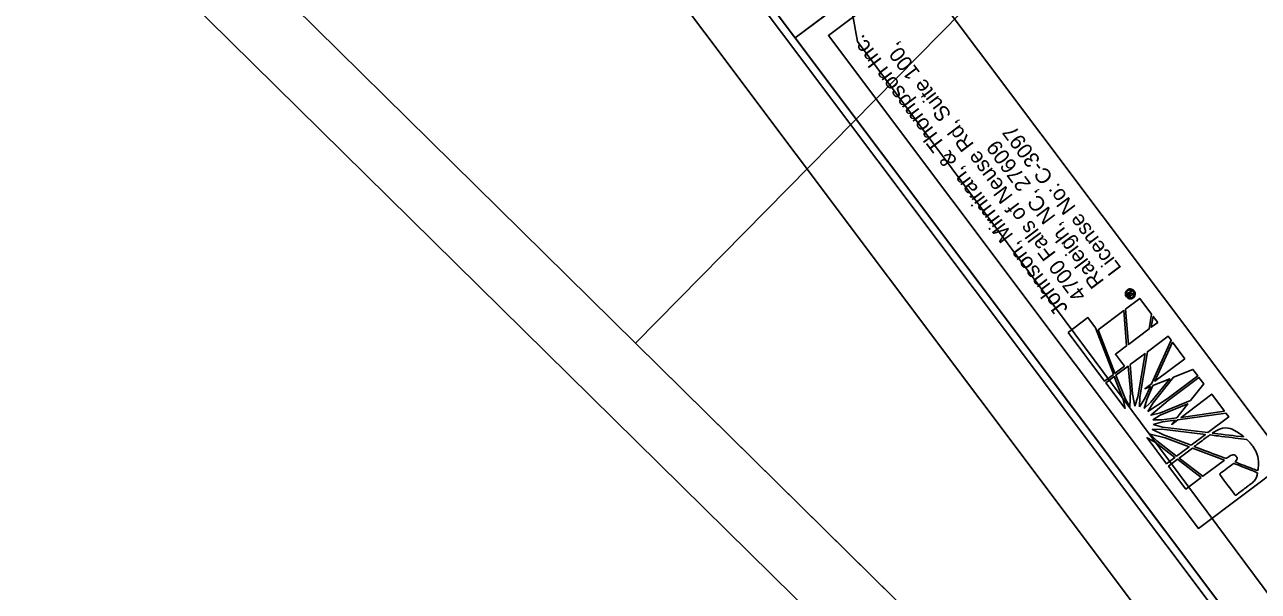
# Model space of a CAD drawing. Extents: x 1265100 to 1267089, y 771887 to 773927.
# Drawn here: x 1265100.1 to 1265500.7, y 772893.1 to 773077 of the extents above; entities that cross this region are included whole.
import ezdxf

# ---------------------------------------------------------------- set-up
doc = ezdxf.new("R2010")
doc.units = 0
for name, color, linetype in [('Exist Utilities Power Pole Cogo Elevation', 7, 'Continuous'), ('Prop Conc 1ft 6in Curb and Gutter', 7, 'Continuous'), ('Prop Conc 4in Sidewalk', 7, 'Continuous'), ('Prop EOT', 7, 'Continuous'), ('Prop Horizontal Alignment Station Label', 7, 'Continuous'), ('Prop Plan Preparation Crest', 7, 'Continuous'), ('Prop Plan Preparation Watershed Post Construction', 7, 'Continuous'), ('Typical Terminator CELL', 7, 'Continuous')]:
    doc.layers.add(name, color=color, linetype=linetype)

msp = doc.modelspace()

# ---------------------------------------------------------------- linework, layer by layer
at = {"layer": 'Exist Utilities Power Pole Cogo Elevation'}
for p, q in [((1265460.15, 772990.34), (1265460.14, 772990.35)), ((1265460.15, 772990.34), (1265460.4, 772990.53)), ((1265460.4, 772990.53), (1265460.15, 772990.34)), ((1265460.39, 772990.54), (1265460.4, 772990.53)), ((1265462.25, 772988.1), (1265457.61, 772984.6)), ((1265457.89, 772988.63), (1265458.13, 772988.81)), ((1265458.13, 772988.81), (1265457.89, 772988.63)), ((1265458.56, 772989.14), (1265458.51, 772989.22)), ((1265458.56, 772989.14), (1265458.78, 772989.31)), ((1265458.78, 772989.31), (1265458.56, 772989.14)), ((1265458.91, 772988.67), (1265458.56, 772989.14)), ((1265458.76, 772989.34), (1265458.78, 772989.31)), ((1265458.78, 772989.31), (1265458.94, 772989.1)), ((1265460.06, 772989.54), (1265458.91, 772988.67)), ((1265458.94, 772989.1), (1265459.21, 772989.3)), ((1265459.05, 772989.51), (1265459.04, 772989.52)), ((1265459.05, 772989.51), (1265459.26, 772989.67)), ((1265459.26, 772989.67), (1265459.05, 772989.51)), ((1265459.21, 772989.3), (1265459.05, 772989.51)), ((1265459.25, 772989.68), (1265459.26, 772989.67)), ((1265459.26, 772989.67), (1265459.42, 772989.46)), ((1265459.42, 772989.46), (1265459.86, 772989.8)), ((1265459.86, 772989.8), (1265460.06, 772989.54)), ((1265466.06, 772983.02), (1265462.25, 772988.1)), ((1265457.02, 772984.17), (1265448.77, 772977.95)), ((1265457.95, 772972.72), (1265457.02, 772984.17)), ((1265457.61, 772984.6), (1265458.56, 772973.18)), ((1265465.25, 772978.22), (1265466.06, 772983.02)), ((1265466.62, 772982.28), (1265465.98, 772978.77)), ((1265468.08, 772980.35), (1265466.62, 772982.28)), ((1265445.37, 772981.88), (1265438.93, 772977.03)), ((1265447.89, 772978.53), (1265445.37, 772981.88)), ((1265453.74, 772963.54), (1265447.89, 772978.53)), ((1265458.56, 772973.18), (1265465.25, 772978.22)), ((1265465.98, 772978.77), (1265468.08, 772980.35)), ((1265438.93, 772977.03), (1265450.76, 772961.3)), ((1265448.77, 772977.95), (1265454.18, 772963.87)), ((1265471.44, 772975.88), (1265464.73, 772970.82)), ((1265466.09, 772960.43), (1265472.44, 772974.56)), ((1265472.44, 772974.56), (1265471.44, 772975.88)), ((1265454.35, 772970.02), (1265457.95, 772972.72)), ((1265463.95, 772970.24), (1265459.16, 772966.64)), ((1265461.62, 772956.15), (1265463.95, 772970.24)), ((1265464.73, 772970.82), (1265462.24, 772956.1)), ((1265472.86, 772973.91), (1265467.17, 772961.24)), ((1265476.89, 772968.55), (1265472.86, 772973.91)), ((1265454.23, 772963.91), (1265457.24, 772966.18)), ((1265457.24, 772966.18), (1265454.35, 772970.02)), ((1265458.49, 772966.13), (1265454.49, 772963.2)), ((1265459.2, 772958), (1265458.49, 772966.13)), ((1265459.16, 772966.64), (1265459.91, 772957.13)), ((1265467.17, 772961.24), (1265476.89, 772968.55)), ((1265450.76, 772961.3), (1265453.65, 772963.48)), ((1265453.93, 772962.77), (1265451.24, 772960.75)), ((1265453.65, 772963.48), (1265453.74, 772963.54)), ((1265456.85, 772955.27), (1265453.93, 772962.77)), ((1265454.18, 772963.87), (1265454.23, 772963.91)), ((1265454.49, 772963.2), (1265457.55, 772955.47)), ((1265473.15, 772962.56), (1265466.55, 772954.24)), ((1265471.09, 772955.51), (1265481.06, 772963.01)), ((1265481.46, 772962.48), (1265471.49, 772954.98)), ((1265479.5, 772965.09), (1265473.15, 772962.56)), ((1265481.06, 772963.01), (1265479.5, 772965.09)), ((1265483.01, 772960.43), (1265481.46, 772962.48)), ((1265451.24, 772960.75), (1265457.44, 772952.43)), ((1265463.91, 772958.78), (1265466.09, 772960.43)), ((1265463.91, 772955.67), (1265465.68, 772959.52)), ((1265465.68, 772959.52), (1265463.91, 772958.78)), ((1265466.53, 772959.85), (1265464.48, 772955.27)), ((1265465.88, 772954.45), (1265471.97, 772962.07)), ((1265471.97, 772962.07), (1265466.53, 772959.85)), ((1265478.67, 772954.97), (1265483.01, 772960.43)), ((1265457.44, 772952.43), (1265456.85, 772955.27)), ((1265457.55, 772955.47), (1265458.99, 772952.94)), ((1265458.99, 772952.94), (1265459.2, 772958)), ((1265459.91, 772957.13), (1265460.64, 772953.16)), ((1265460.64, 772953.16), (1265461.62, 772956.15)), ((1265462.24, 772956.1), (1265462.2, 772952.96)), ((1265462.2, 772952.96), (1265463.91, 772955.67)), ((1265464.48, 772955.27), (1265463.67, 772952.4)), ((1265463.67, 772952.4), (1265465.88, 772954.45)), ((1265464.9, 772951.45), (1265471.09, 772955.51)), ((1265466.55, 772954.24), (1265464.9, 772951.45)), ((1265471.49, 772954.98), (1265465.83, 772950.22)), ((1265469, 772950.99), (1265478.67, 772954.97)), ((1265485.59, 772957.08), (1265475.65, 772949.52)), ((1265489.79, 772951.5), (1265485.59, 772957.08)), ((1265465.83, 772950.22), (1265469, 772950.99)), ((1265468.89, 772950.26), (1265466.43, 772948.73)), ((1265477.82, 772953.94), (1265468.89, 772950.26)), ((1265474.23, 772949.36), (1265477.82, 772953.94)), ((1265490.22, 772950.92), (1265474.58, 772948.72)), ((1265475.65, 772949.52), (1265489.79, 772951.5)), ((1265491.15, 772949.68), (1265490.22, 772950.92)), ((1265466.43, 772948.73), (1265469.44, 772948.68)), ((1265469.65, 772948.04), (1265466.57, 772947.16)), ((1265466.57, 772947.16), (1265469.59, 772946.32)), ((1265469.44, 772948.68), (1265474.23, 772949.36)), ((1265469.59, 772946.32), (1265484.36, 772944.58)), ((1265473.68, 772948.62), (1265469.65, 772948.04)), ((1265474.58, 772948.72), (1265472.6, 772947.23)), ((1265472.6, 772947.23), (1265473.68, 772948.62)), ((1265484.36, 772944.58), (1265491.15, 772949.68)), ((1265467.18, 772941.47), (1265464.61, 772942.9)), ((1265464.61, 772942.9), (1265470.94, 772934.48)), ((1265470.47, 772942.92), (1265465.62, 772944.12)), ((1265465.62, 772944.12), (1265467.76, 772941.9)), ((1265469.43, 772945.69), (1265466.32, 772945.61)), ((1265466.32, 772945.61), (1265469.91, 772943.85)), ((1265483.57, 772943.98), (1265469.43, 772945.69)), ((1265469.91, 772943.85), (1265478.91, 772940.47)), ((1265478.25, 772939.98), (1265470.47, 772942.92)), ((1265478.91, 772940.47), (1265483.57, 772943.98)), ((1265473.62, 772936.5), (1265467.18, 772941.47)), ((1265467.76, 772941.9), (1265474.2, 772936.93)), ((1265474.2, 772936.93), (1265478.25, 772939.98)), ((1265479.33, 772939.57), (1265475, 772936.31)), ((1265489.7, 772935.66), (1265479.33, 772939.57)), ((1265470.94, 772934.48), (1265473.62, 772936.5)), ((1265474.45, 772935.9), (1265471.57, 772933.73)), ((1265482.16, 772929.98), (1265474.45, 772935.9)), ((1265475, 772936.31), (1265482.72, 772930.41)), ((1265482.72, 772930.41), (1265489.7, 772935.66)), ((1265471.57, 772933.73), (1265477.2, 772926.25)), ((1265477.2, 772926.25), (1265482.16, 772929.98))]:
    msp.add_line(p, q, dxfattribs=at)
msp.add_lwpolyline([(1265510.12, 772935.14), (1265390, 773095.1), (1265361.13, 773073.42), (1265481.26, 772913.47)], close=True, dxfattribs=at)
for points in [[(1265459.06, 772990.3), (1265459.12, 772990.35), (1265459.16, 772990.39), (1265459.2, 772990.42), (1265459.3, 772990.54), (1265459.48, 772990.3)], [(1265458.56, 772973.18), (1265465.25, 772978.22), (1265466.06, 772983.02), (1265462.25, 772988.1), (1265457.61, 772984.6), (1265458.56, 772973.18), (1265458.56, 772973.18)], [(1265454.18, 772963.87), (1265454.23, 772963.91), (1265457.24, 772966.18), (1265454.35, 772970.02), (1265457.95, 772972.72), (1265457.02, 772984.17), (1265448.77, 772977.95), (1265454.18, 772963.87)], [(1265468.08, 772980.35), (1265468.08, 772980.35), (1265466.62, 772982.28), (1265465.98, 772978.77), (1265468.08, 772980.35)], [(1265438.93, 772977.03), (1265450.76, 772961.3), (1265453.65, 772963.48), (1265453.74, 772963.54), (1265447.89, 772978.53), (1265445.37, 772981.88), (1265438.93, 772977.03)], [(1265462.2, 772952.96), (1265463.91, 772955.67), (1265465.68, 772959.52), (1265463.91, 772958.78), (1265466.09, 772960.43), (1265472.44, 772974.56), (1265471.44, 772975.88), (1265464.73, 772970.82), (1265462.24, 772956.1), (1265462.2, 772952.96)], [(1265460.64, 772953.16), (1265461.62, 772956.15), (1265463.95, 772970.24), (1265459.16, 772966.64), (1265459.91, 772957.13), (1265460.64, 772953.16)], [(1265476.89, 772968.55), (1265472.86, 772973.91), (1265467.17, 772961.24), (1265476.89, 772968.55)], [(1265458.99, 772952.94), (1265459.2, 772958), (1265458.49, 772966.13), (1265454.49, 772963.2), (1265457.55, 772955.47), (1265458.99, 772952.94)], [(1265456.85, 772955.27), (1265453.93, 772962.77), (1265451.24, 772960.75), (1265457.44, 772952.43), (1265456.85, 772955.27)], [(1265464.9, 772951.45), (1265471.09, 772955.51), (1265481.06, 772963.01), (1265479.5, 772965.09), (1265473.15, 772962.56), (1265466.55, 772954.24), (1265464.9, 772951.45)], [(1265469, 772950.99), (1265478.67, 772954.97), (1265483.01, 772960.43), (1265481.46, 772962.48), (1265471.49, 772954.98), (1265465.83, 772950.22), (1265469, 772950.99)], [(1265463.67, 772952.4), (1265465.88, 772954.45), (1265471.97, 772962.07), (1265466.53, 772959.85), (1265464.48, 772955.27), (1265463.67, 772952.4)], [(1265489.79, 772951.5), (1265485.59, 772957.08), (1265475.65, 772949.52), (1265489.79, 772951.5)], [(1265466.43, 772948.73), (1265469.44, 772948.68), (1265474.23, 772949.36), (1265477.82, 772953.94), (1265468.89, 772950.26), (1265466.43, 772948.73)], [(1265466.57, 772947.16), (1265469.59, 772946.32), (1265484.36, 772944.58), (1265491.15, 772949.68), (1265490.22, 772950.92), (1265474.58, 772948.72), (1265472.6, 772947.23), (1265473.68, 772948.62), (1265469.65, 772948.04), (1265466.57, 772947.16)], [(1265467.18, 772941.47), (1265464.61, 772942.9), (1265470.94, 772934.48), (1265473.62, 772936.5), (1265467.18, 772941.47)], [(1265474.2, 772936.93), (1265478.25, 772939.98), (1265470.47, 772942.92), (1265465.62, 772944.12), (1265467.76, 772941.9), (1265474.2, 772936.93)], [(1265478.91, 772940.47), (1265483.57, 772943.98), (1265469.43, 772945.69), (1265466.32, 772945.61), (1265469.91, 772943.85), (1265478.91, 772940.47)], [(1265489.7, 772935.66), (1265479.33, 772939.57), (1265475, 772936.31), (1265482.72, 772930.41), (1265489.7, 772935.66)], [(1265482.16, 772929.98), (1265474.45, 772935.9), (1265471.57, 772933.73), (1265477.2, 772926.25), (1265482.16, 772929.98)]]:
    msp.add_lwpolyline(points, dxfattribs=at)
for points, degree in [([(1265457.89, 772988.63), (1265457.62, 772988.99), (1265457.52, 772989.38), (1265457.57, 772989.81), (1265457.61, 772990.23), (1265457.82, 772990.59), (1265458.17, 772990.85)], 3), ([(1265460.14, 772990.35), (1265459.93, 772990.63), (1265459.66, 772990.8), (1265459.31, 772990.85), (1265458.97, 772990.9), (1265458.64, 772990.81), (1265458.36, 772990.6), (1265458.08, 772990.39), (1265457.91, 772990.1), (1265457.86, 772989.75), (1265457.82, 772989.41), (1265457.91, 772989.11), (1265458.13, 772988.81)], 3), ([(1265460.4, 772990.53), (1265460.66, 772990.18), (1265460.76, 772989.79), (1265460.7, 772989.35), (1265460.65, 772988.92), (1265460.44, 772988.57), (1265460.09, 772988.3), (1265459.73, 772988.04), (1265459.34, 772987.94), (1265458.92, 772988.01), (1265458.5, 772988.08), (1265458.15, 772988.28), (1265457.89, 772988.63)], 3), ([(1265458.13, 772988.81), (1265458.34, 772988.53), (1265458.61, 772988.36), (1265458.95, 772988.31), (1265459.29, 772988.26), (1265459.62, 772988.34), (1265459.9, 772988.55), (1265460.18, 772988.77), (1265460.35, 772989.06), (1265460.4, 772989.4), (1265460.45, 772989.75), (1265460.36, 772990.06), (1265460.15, 772990.34)], 3), ([(1265458.17, 772990.85), (1265458.53, 772991.12), (1265458.92, 772991.22), (1265459.35, 772991.17), (1265459.78, 772991.1), (1265460.13, 772990.89), (1265460.39, 772990.54)], 3), ([(1265458.87, 772989.96), (1265458.86, 772990.07), (1265458.92, 772990.18), (1265459.06, 772990.3)], 2), ([(1265459.48, 772990.3), (1265459.44, 772990.23), (1265459.39, 772990.16), (1265459.31, 772990.1), (1265459.21, 772990.02), (1265459.15, 772989.96), (1265459.14, 772989.91)], 3), ([(1265458.51, 772989.22), (1265458.29, 772989.51), (1265458.29, 772989.74), (1265458.52, 772989.91), (1265458.63, 772989.99), (1265458.74, 772990.01), (1265458.87, 772989.96)], 3), ([(1265459.04, 772989.52), (1265458.92, 772989.69), (1265458.8, 772989.73), (1265458.71, 772989.66), (1265458.63, 772989.6), (1265458.64, 772989.49), (1265458.76, 772989.34)], 3), ([(1265459.14, 772989.91), (1265459.15, 772989.86), (1265459.17, 772989.78), (1265459.25, 772989.68)], 2), ([(1265485.77, 772944.42), (1265485.77, 772944.42), (1265496.17, 772943.12), (1265496.17, 772943.12), (1265493.32, 772945.44), (1265489.3, 772946.86), (1265485.77, 772944.42)], 3), ([(1265493.53, 772936.86), (1265493.87, 772936.42), (1265493.91, 772935.85), (1265493.2, 772935.06), (1265493.2, 772935.06), (1265500.56, 772932.19), (1265500.56, 772932.19), (1265501.06, 772935.16), (1265500.11, 772938.58), (1265498.42, 772940.81), (1265497.99, 772941.39), (1265497.6, 772941.8), (1265497.02, 772942.32), (1265497.02, 772942.32), (1265484.98, 772943.83), (1265484.98, 772943.83), (1265484.98, 772943.83), (1265479.95, 772940.04), (1265479.95, 772940.04), (1265479.95, 772940.04), (1265490.33, 772936.13), (1265490.33, 772936.13), (1265492.22, 772937.55), (1265493.07, 772937.48), (1265493.53, 772936.86)], 3), ([(1265493.53, 772936.86), (1265493.87, 772936.42), (1265493.91, 772935.85), (1265493.2, 772935.06), (1265493.2, 772935.06), (1265500.56, 772932.19), (1265500.56, 772932.19), (1265501.06, 772935.16), (1265500.11, 772938.58), (1265498.42, 772940.81), (1265497.99, 772941.39), (1265497.6, 772941.8), (1265497.02, 772942.32), (1265497.02, 772942.32), (1265484.98, 772943.83), (1265484.98, 772943.83), (1265484.98, 772943.83), (1265479.95, 772940.04), (1265479.95, 772940.04), (1265479.95, 772940.04), (1265490.33, 772936.13), (1265490.33, 772936.13), (1265492.22, 772937.55), (1265493.07, 772937.48), (1265493.53, 772936.86)], 3), ([(1265488.11, 772931.1), (1265488.11, 772931.1), (1265493.32, 772924.17), (1265493.32, 772924.17), (1265493.32, 772924.17), (1265497.65, 772927.43), (1265497.65, 772927.43), (1265497.65, 772927.43), (1265498.11, 772927.78), (1265498.11, 772927.78), (1265499.46, 772928.8), (1265500.2, 772930.05), (1265500.51, 772931.52), (1265500.51, 772931.52), (1265492.77, 772934.61), (1265492.69, 772934.54), (1265492.69, 772934.54), (1265488.11, 772931.1), (1265488.11, 772931.1)], 3)]:
    msp.add_open_spline(points, degree=degree, dxfattribs=at)
at = {"layer": 'Prop Conc 1ft 6in Curb and Gutter'}
for points in [[(1265230.23, 773232.7), (1266131, 772033.24), (1266970.61, 772663.76), (1266069.85, 773863.21)], [(1266970.61, 772663.76), (1266131.04, 772033.23), (1265350.36, 773072.71), (1265470.35, 773162.83), (1265350.24, 773322.8), (1266069.85, 773863.21)], [(1265350.36, 773072.71), (1265230.23, 773232.7), (1265250.28, 773247.72), (1265370.42, 773087.78)]]:
    msp.add_lwpolyline(points, close=True, dxfattribs=at)
at = {"layer": 'Prop Conc 4in Sidewalk'}
msp.add_line((1265100.13, 773137.46), (1266299.32, 771955.88), dxfattribs=at)
at = {"layer": 'Prop EOT'}
msp.add_lwpolyline([(1267064.78, 772542.54), (1266064.35, 773874.7), (1265220.75, 773241.19), (1266221.18, 771909.01)], close=True, dxfattribs=at)
at = {"layer": 'Prop Horizontal Alignment Station Label'}
msp.add_lwpolyline([(1267088.58, 772544.15), (1266077.64, 773890.32), (1265202.05, 773232.77), (1266212.99, 771886.61)], close=True, dxfattribs=at)
at = {"layer": 'Prop Plan Preparation Crest'}
for points in [[(1266196.55, 772088.75), (1266933.46, 772836.68), (1265864.98, 773889.47), (1265276.47, 773292.18), (1265446.89, 773124.26), (1265298.46, 772973.62)], [(1265446.89, 773124.26), (1265276.45, 773292.2), (1265128, 773141.57), (1265298.46, 772973.62)]]:
    msp.add_lwpolyline(points, close=True, dxfattribs=at)
at = {"layer": 'Prop Plan Preparation Watershed Post Construction'}
msp.add_lwpolyline([(1266897.84, 772871.78), (1265900.59, 773854.39), (1265312.07, 773257.1), (1265446.89, 773124.26), (1265298.46, 772973.62), (1266160.9, 772123.84)], close=True, dxfattribs=at)
at = {"layer": 'Typical Terminator CELL'}
msp.add_lwpolyline([(1266289.35, 772153.62), (1266298.14, 772160.44), (1266307.8, 772184.21), (1266331.91, 772215.31), (1266332.35, 772261.45), (1266387.5, 772467.54), (1266710.25, 772749.07), (1266813.62, 772836.44), (1266224.27, 773631.5), (1266145.65, 773582.41), (1265981.26, 773779.69), (1265375.94, 773334.64), (1265484.1, 773191.06), (1265496.18, 773177.78), (1265368.96, 773080.53), (1265370.53, 773071.49), (1265889.02, 772374.44), (1265992.81, 772219.74), (1266130.48, 772035.91)], close=True, dxfattribs=at)

# ---------------------------------------------------------------- texts
at = {"layer": 'Exist Utilities Power Pole Cogo Elevation'}
for s, height, p in [('Johnson, Mirmiran, & Thompson Inc.', 5.1112, (1265439.18, 772984.89)), ('4700 Falls of Neuse Rd, Suite 100, ', 4.9652, (1265445.18, 772989.39)), ('License No: C-3097', 4.9652, (1265456.52, 772997.92)), ('Raleigh, NC, 27609', 4.9652, (1265450.85, 772993.65))]:
    msp.add_text(s, height=height, rotation=126.9057, dxfattribs=at).set_placement(p)

doc.saveas('drawing.dxf')
